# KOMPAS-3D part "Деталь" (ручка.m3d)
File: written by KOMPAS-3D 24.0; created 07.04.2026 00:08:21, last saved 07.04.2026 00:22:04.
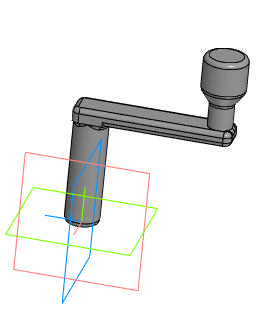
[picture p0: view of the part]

Document properties: Автор: R2D2; Полное имя файла: E:\Работа\Зайцев\Солянка\VSR1-13V-PED-F Клапан запорно-регулирующий DN.ru\DN15\DN15 Kv0.16\исходные материалы\ручка.m3d

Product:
- Part/product: Деталь
    Масса: 0.134709

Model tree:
1. Эскиз:1
2. Элемент выдавливания:1
     Расстояние 1 = 50
3. Эскиз:2  (with: Грань.Элемент выдавливания:1, Ребро.Элемент выдавливания:1)
4. Элемент выдавливания:2
     Расстояние 2 = 6
5. Эскиз:3  (with: Вершина.Элемент выдавливания:2, Ребро.Элемент выдавливания:2)
6. Элемент вращения:1
     Угол 1 = 360
7. Скругление:1  (with: Ребро.Элемент выдавливания:2)
     Радиус = 3
8. Скругление:2  (with: Грань.Элемент выдавливания:1)
     Радиус = 2
9. Скругление:3  (with: Грань.Элемент вращения:1, Грань.Элемент выдавливания:2)
     Радиус = 2

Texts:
  Линейный размер с обрывом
